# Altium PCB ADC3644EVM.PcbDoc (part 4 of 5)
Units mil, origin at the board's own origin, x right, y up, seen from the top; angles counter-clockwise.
Board outline 3900 x 2716.54 mil, 10 copper layers (Top Layer, L2 GND, L3 PWR, L4 GND, L5 SIG, L6 GND, L7 GND, L8 PWR, L9 GND, Bottom Layer), stack 61.2 mil thick; 368 components, 252 nets, 1539 pads, 1019 vias.
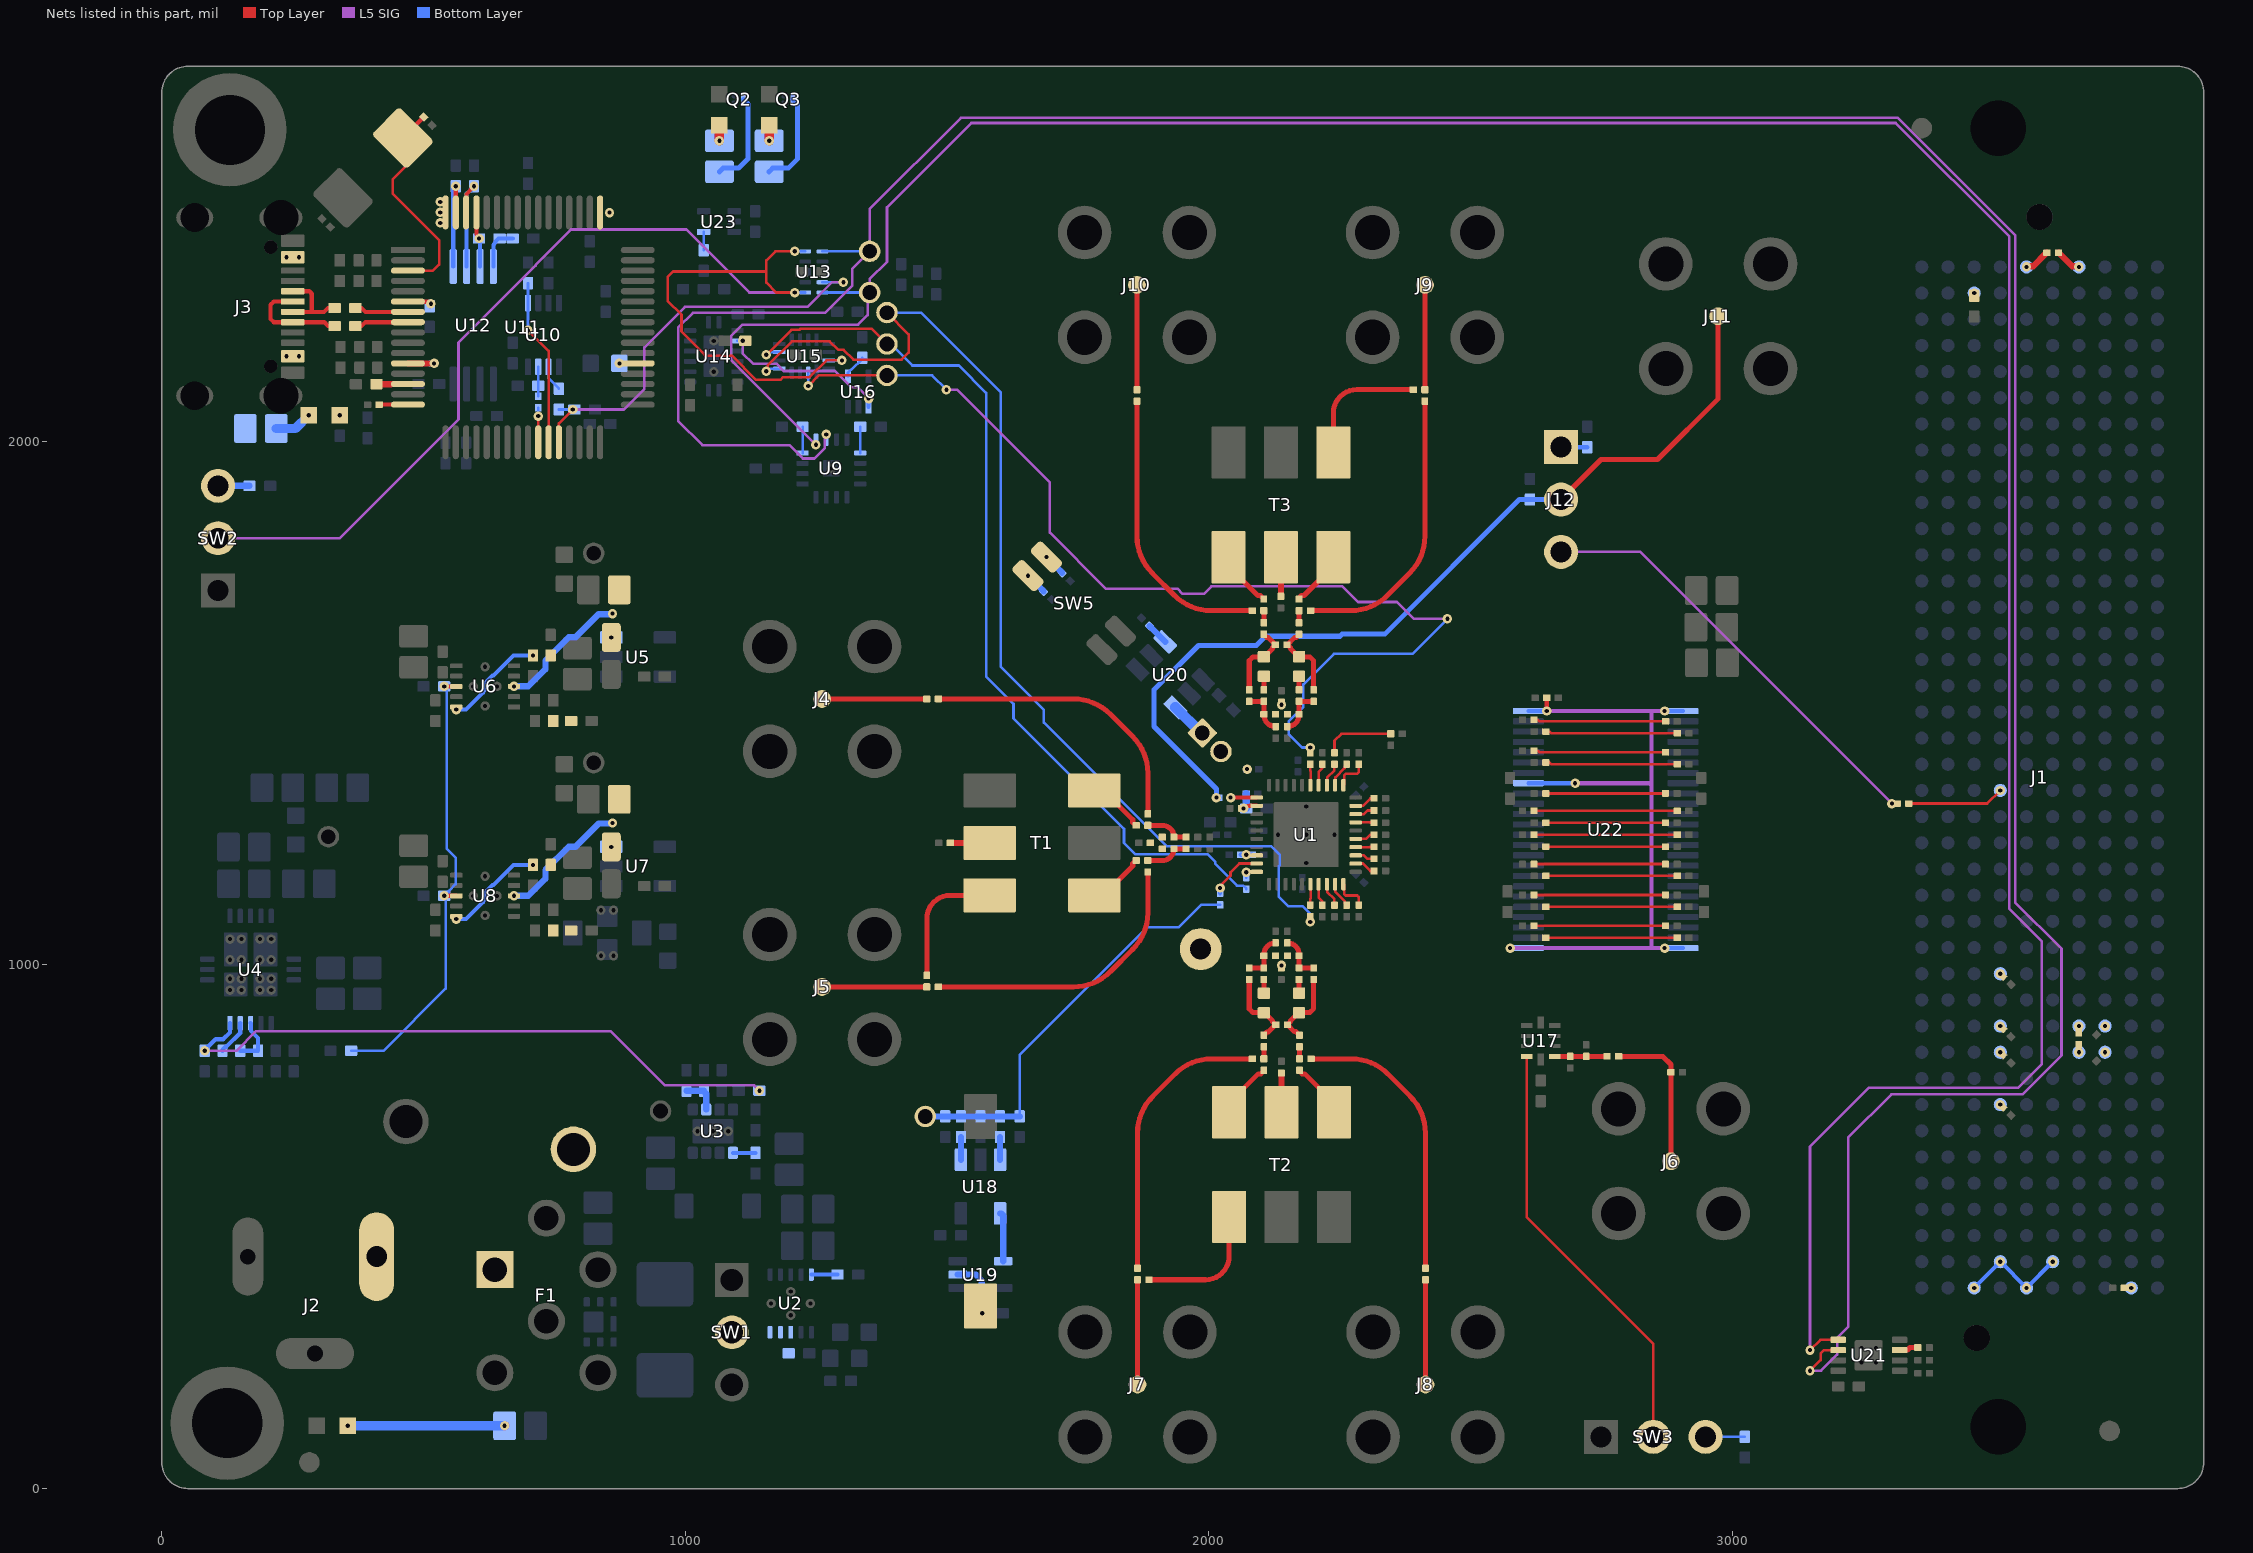
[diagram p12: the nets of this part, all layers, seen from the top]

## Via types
v1: diameter 18, hole 8, Top Layer to Bottom Layer, tented both sides, 1001 vias
v2: diameter 40, hole 20, Top Layer to Bottom Layer, tented both sides, 14 vias
v3: diameter 18, hole 8, Top Layer to Bottom Layer, tented bottom, 4 vias

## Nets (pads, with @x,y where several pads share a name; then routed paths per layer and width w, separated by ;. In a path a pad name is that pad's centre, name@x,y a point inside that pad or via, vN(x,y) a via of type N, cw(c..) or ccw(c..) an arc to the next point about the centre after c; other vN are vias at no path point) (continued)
NetC43_2: C43.2 U11.3 Y1.2 | length 411.4
  Top Layer w5: Y1.2@460.25,2579.29 465.25,2574.29 465.25,2524.93 440.9,2500.58 440.9,2472.95 529.61,2384.23 529.61,2337.89 517.8,2326.08 U11.3@470,2326.08
  Top Layer w8: Y1.2@460.25,2579.29 C43.2@500.25,2619.29
NetC48_1: C48.1 C49.2 R63.2 R65.2 | length 85.7
  Top Layer w9.7: C49.2@1883.16,1266.57 1910.93,1266.57 cw(c1910.93,1244.35) R65.2@1933.16,1244.35 C48.1@1956.16,1244.35
NetC49_1: C49.1 T1.6 | length 110.3
  Top Layer w9.7: T1.6@1781.11,1333.05 1798.61,1333.05 1854.39,1277.27 1854.39,1272.5 1860.32,1266.57 C49.1@1861.11,1266.57
NetC50_1: C50.1 T1.2 | length 75
  Top Layer w12: C50.1@1506.11,1233.05 T1.2@1581.11,1233.05
NetC51_2: C51.2 R65.1 R67.2
NetC52_1: C52.1 T1.3 | length 253.6
  Top Layer w9.7: C52.1@1461.11,980.1 1461.11,1088.05 cw(c1506.11,1088.05) 1506.11,1133.05 T1.3@1581.11,1133.05
NetC53_1: C53.1 C54.1 R67.1 R69.2 | length 85.7
  Top Layer w9.7: C53.1@1883.16,1199.53 1910.93,1199.53 ccw(c1910.93,1221.75) R67.1@1933.16,1221.75 C54.1@1956.16,1221.75
NetC53_2: C53.2 T1.4 | length 110.3
  Top Layer w9.7: T1.4@1781.11,1133.05 1798.61,1133.05 1854.39,1188.83 1854.39,1193.6 1860.32,1199.53 C53.2@1861.11,1199.53
NetC56_1: C56.1 R70.1 R72.2 U17.1 | length 100
  Top Layer w9.7: U17.1@2660.22,825.27 R70.1@2690.22,825.27 R72.2@2720.22,825.27 C56.1@2760.22,825.27
NetC56_2: C56.2 J6.1 R71.2 | length 290.9
  Top Layer w9.7: C56.2@2782.27,825.27 2866.74,825.27 2882.27,809.74 R71.2@2882.27,795.27 J6.1@2882.27,625.27
NetC57_1: C57.1 C58.1 J7.1 | length 200
  Top Layer w9.7: J7.1@1863.45,198.72 C57.1@1863.45,398.72
NetC57_2: C57.2 R74.1 | length 551.9
  Top Layer w9.7: C57.2@1863.45,420.77 1863.45,678.69 cw(c1963.45,678.69) 1892.74,749.4 1935.34,792 cw(c2004.78,722.56) 2004.78,820.77 R74.1@2082.88,820.77
NetC58_2: C58.2 T2.1 | length 253.6
  Top Layer w9.7: C58.2@1885.49,398.72 1993.45,398.72 ccw(c1993.45,443.72) 2038.45,443.72 T2.1@2038.45,518.72
NetC59_1: C59.1 T2.6 | length 110.3
  Top Layer w9.7: T2.6@2038.45,718.72 2038.45,736.22 2094.23,792 2098.99,792 2104.93,797.93 C59.1@2104.93,798.72
NetC59_2: C59.2 R74.2 R75.1 | length 23
  Top Layer w9.7: C59.2@2104.93,820.77 R75.1@2104.93,843.77
NetC60_1: C60.1 T2.5 | length 75
  Top Layer w12: T2.5@2138.45,718.72 C60.1@2138.45,793.72
NetC62_1: C62.1 L2.1 R83.2 R84.1 | length 150.7
  Top Layer w9.7: C62.1@2148.97,885.81 C62.1@2149.76,885.81 ; R83.2@2171.97,865.81 2171.97,866.6 2166.04,872.53 2163.04,872.53 C62.1@2149.76,885.81 ; R84.1@2199.97,971.43 2199.97,916.45 2192.65,909.13 2172.29,909.13 L2.1@2171.97,908.81 2170.98,908.81 2155.69,893.52 2155.69,891.74 C62.1@2149.76,885.81
NetC62_2: C62.2 L1.1 R75.2 R76.1 | length 150.7
  Top Layer w9.7: R76.1@2076.93,971.2 2076.93,916.22 2084.25,908.9 2104.61,908.9 2104.93,908.58 2105.91,908.58 2121.21,893.28 2121.21,891.51 C62.2@2127.14,885.58 ; R75.2@2104.93,865.58 2104.93,866.37 2110.86,872.3 2113.86,872.3 C62.2@2127.14,885.58 ; C62.2@2127.93,885.58 C62.2@2127.14,885.58
NetC63_1: C63.1 R82.2 R83.1 | length 23
  Top Layer w9.7: C63.1@2172.95,820.77 R83.1@2172.95,843.77
NetC63_2: C63.2 T2.4 | length 110.3
  Top Layer w9.7: C63.2@2171.97,798.72 2171.97,797.93 2177.9,792 2182.66,792 2238.45,736.22 T2.4@2238.45,718.72
NetC64_1: C64.1 J8.1 | length 200
  Top Layer w9.7: J8.1@2413.45,198.72 C64.1@2413.45,398.72
NetC64_2: C64.2 R82.1 | length 551.9
  Top Layer w9.7: R82.1@2194.02,820.77 2272.11,820.77 cw(c2272.11,722.56) 2341.56,792 2384.16,749.4 cw(c2313.45,678.69) 2413.45,678.69 C64.2@2413.45,420.77
NetC65_1: C65.1 C66.1 J9.1 | length 200
  Top Layer w9.7: C65.1@2412.46,2098.88 J9.1@2412.46,2298.88
NetC65_2: C65.2 R86.1 | length 551.9
  Top Layer w9.7: R86.1@2193.03,1676.83 2271.13,1676.83 ccw(c2271.13,1775.04) 2340.57,1705.59 2383.17,1748.19 ccw(c2312.46,1818.9) 2412.46,1818.9 C65.2@2412.46,2076.83
NetC66_2: C66.2 T3.1 | length 253.6
  Top Layer w9.7: T3.1@2237.46,1978.88 2237.46,2053.88 cw(c2282.46,2053.88) 2282.46,2098.88 C66.2@2390.42,2098.88
NetC67_1: C67.1 T3.6 | length 110.3
  Top Layer w9.7: C67.1@2170.98,1698.88 2170.98,1699.66 2176.91,1705.59 2181.68,1705.59 2237.46,1761.38 T3.6@2237.46,1778.88
NetC67_2: C67.2 R86.2 R87.1 | length 23
  Top Layer w9.7: R87.1@2171.97,1653.83 C67.2@2171.97,1676.83
NetC69_1: C69.1 T3.5 | length 75
  Top Layer w12: C69.1@2137.46,1703.88 T3.5@2137.46,1778.88
NetC70_1: C70.1 L4.1 R95.2 R96.1 | length 150.7
  Top Layer w9.7: R96.1@2076.93,1526.17 2076.93,1581.14 2084.25,1588.46 2104.61,1588.46 L4.1@2104.93,1588.78 2105.91,1588.78 2121.21,1604.08 2121.21,1605.85 C70.1@2127.14,1611.78 ; R95.2@2104.93,1631.78 2104.93,1630.99 2110.86,1625.06 2113.86,1625.06 C70.1@2127.14,1611.78 ; C70.1@2127.93,1611.78 C70.1@2127.14,1611.78
NetC70_2: C70.2 L3.1 R87.2 R88.1 | length 150.7
  Top Layer w9.7: C70.2@2148.97,1611.78 C70.2@2149.76,1611.78 ; R87.2@2171.97,1631.78 2171.97,1630.99 2166.04,1625.06 2163.04,1625.06 C70.2@2149.76,1611.78 ; R88.1@2199.97,1526.17 2199.97,1581.14 2192.65,1588.46 2172.29,1588.46 L3.1@2171.97,1588.78 2170.98,1588.78 2155.69,1604.08 2155.69,1605.85 C70.2@2149.76,1611.78
NetC71_1: C71.1 R94.2 R95.1 | length 23
  Top Layer w9.7: R95.1@2104.93,1653.83 C71.1@2104.93,1676.83
NetC71_2: C71.2 T3.4 | length 110.3
  Top Layer w9.7: T3.4@2037.46,1778.88 2037.46,1761.38 2093.24,1705.59 2098.01,1705.59 2103.94,1699.66 C71.2@2103.94,1698.88
NetC72_1: C72.1 J10.1 | length 200
  Top Layer w9.7: C72.1@1862.46,2098.88 J10.1@1862.46,2298.88
NetC72_2: C72.2 R94.1 | length 551.9
  Top Layer w9.7: C72.2@1862.46,2076.83 1862.46,1818.9 ccw(c1962.46,1818.9) 1891.75,1748.19 1934.35,1705.59 ccw(c2003.8,1775.04) 2003.8,1676.83 R94.1@2081.89,1676.83
NetD1_2: D1.2 R3.2 | length 300
  Bottom Layer w18: v1(355,120) R3.2@655,120
  other v1: 654.67,119.85
NetD4_2: D4.2 R18.2 | length 30
  Top Layer w18: v1(1065,2574.06) D4.2@1065,2604.06
NetD5_2: D5.2 R25.2 | length 30
  Top Layer w18: v1(1160,2574.06) D5.2@1160,2604.06
NetD6_2: D6.2 R45.2
  other v1: 340,2050
NetF1_1: F1.1 J2.1 TP1.1
NetFB2_1: FB2.1 R17.2 U5.3 U6.8 | length 255.5
  Bottom Layer w12: v1(672.65,1532.05) 700.02,1532.05 732.72,1564.76 732.72,1581.32 777.41,1626.01 790.09,1626.01 834.05,1669.98 859.68,1669.98 v1(860.83,1671.12)
  other v1: 858.46,1625.55
NetFB3_1: FB3.1 R27.2 U7.3 U8.8 | length 255.5
  Bottom Layer w12: v1(672.65,1132.05) 700.02,1132.05 732.72,1164.76 732.72,1181.32 777.41,1226.01 790.09,1226.01 834.05,1269.98 859.68,1269.98 v1(860.83,1271.12)
  other v1: 858.46,1225.55
NetJ1_B40: J1.B40 R145.2 | length 13.3
  Top Layer w10: R145.2@3748.13,383.27 v1(3761.42,383.27)
NetJ1_G21: J1.G21 R141.2 | length 185.4
  Top Layer w5: R141.2@3336.42,1308.27 3486.42,1308.27 v1(3511.42,1333.27)
NetJ1_G28: J1.G28 R142.2 | length 6.7
  Top Layer w5: v1(3511.42,983.27) R142.2@3516.12,978.56
NetJ1_G30: J1.G30 R143.2 | length 6.7
  Top Layer w5: v1(3511.42,883.27) R143.2@3516.12,878.56
NetJ1_G31: J1.G31 R144.2 | length 6.7
  Top Layer w5: v1(3511.42,833.27) R144.2@3516.12,828.56
NetJ1_G33: J1.G33 R146.2 | length 6.7
  Top Layer w5: v1(3511.42,733.27) R146.2@3516.12,728.56
NetJ3_A4,B4: J3.A4 J3.B4 R42.1
  other v1: 238.16,2162.69 262.16,2162.69 238.16,2351.67 262.16,2351.67
NetJ3_A6: J3.A6 J3.B6 R44.1 | length 200
  Top Layer w8: J3.B6@245.62,2227.65 213.91,2227.65 207.83,2233.72 207.83,2260.95 213.91,2267.02 J3.A6@250.16,2267.02 ; J3.B6@245.63,2227.65 J3.B6@250.16,2227.65 310.15,2227.65 317.56,2220.25 R44.1@330.16,2220.25
NetJ3_A7: J3.A7 J3.B7 R43.1 | length 155.9
  Top Layer w8: J3.A7@250.16,2247.34 286.41,2247.34 ; J3.B7@250.16,2286.71 281.72,2286.71 286.41,2282.02 286.41,2247.34 ; R43.1@330.16,2254.74 317.32,2254.74 309.91,2247.34 286.41,2247.34
NetJ11_1: J11.1 J12.2 R101.2 R118.1 | length 1725.3
  Top Layer w9.7: J12.2@2672.46,1888.88 2748.84,1965.25 2856.45,1965.25 2972.46,2081.26 J11.1@2972.46,2238.88
  Bottom Layer w9.7: R118.1@2019.37,1319.66 2014.37,1319.66 2014.37,1336.14 1895.21,1455.29 1895.21,1525.59 1979.93,1610.3 2090.5,1610.3 2107.96,1627.76 2250.14,1627.76 2254.22,1631.83 2335.71,1631.83 2592.75,1888.88 R101.2@2612.93,1888.88 J12.2@2672.46,1888.88
  other v1: 2014.16,1319.66
NetJ12_1: J12.1 R110.1 | length 50
  Bottom Layer w8: J12.1@2672.46,1988.88 R110.1@2722.46,1988.88
NetJ13_1: J13.1 U20.6 | length 69.1
  Bottom Layer w20: U20.6@1935.98,1491.88 J13.1@1984.82,1443.04
NetL1_2: L1.2 R78.1 | length 26
  Top Layer w9.7: L1.2@2104.93,946.22 R78.1@2104.93,972.22
NetL2_2: L2.2 R81.1 | length 26
  Top Layer w9.7: L2.2@2171.97,946.22 R81.1@2171.97,972.22
NetL3_2: L3.2 R90.1 | length 26
  Top Layer w9.7: R90.1@2171.97,1525.38 L3.2@2171.97,1551.38
NetL4_2: L4.2 R93.1 | length 26
  Top Layer w9.7: R93.1@2104.93,1525.38 L4.2@2104.93,1551.38
NetQ2_3: Q2.3 R18.1 | length 181.6
  Bottom Layer w9.7: R18.1@1065,2515 1071.82,2521.82 1101.43,2521.82 1119.42,2539.81 1119.42,2644.44 Q2.3@1110.75,2653.11
NetQ3_3: Q3.3 R25.1 | length 181.6
  Bottom Layer w9.7: R25.1@1160,2515 1166.82,2521.82 1196.43,2521.82 1214.42,2539.81 1214.42,2644.44 Q3.3@1205.75,2653.11
NetR1_2: R1.2 SW1.2 U2.3 U2.4 U2.5
NetR2_2: R2.2 U2.10 | length 50
  Bottom Layer w8: U2.10@1240.59,408.64 R2.2@1290.59,408.64
NetR6_1: R6.1 U3.1 | length 43
  Bottom Layer w8: U3.1@1090.88,641.15 R6.1@1133.88,641.15
NetR7_1: R7.1 R8.2 U3.6 | length 71.3
  Bottom Layer w12: R8.2@1002.1,759.83 R7.1@1035.7,759.83 1035.7,757.86 1039.7,753.86 U3.6@1039.7,723.83
NetR9_1: R9.1 R11.1 U4.24 | length 1204
  L5 SIG w5: v1(81.89,836.12) 142.5,836.12 179.96,873.58 857.24,873.58 960.83,770 1131.23,770 v1(1141.4,759.83)
  Bottom Layer w8: v1(81.89,836.12) 81.89,838.09 87.73,843.93 88.74,843.93 103.07,858.26 117.42,858.26 130.21,871.05 U4.24@130.21,888.94
NetR12_1: R12.1 R14.2 U4.22 | length 92.7
  Bottom Layer w8: R14.2@149.89,836.12 R12.1@183.89,836.12 183.89,860.44 170.5,873.83 170.5,888.02 U4.22@169.58,888.94
NetR13_2: R13.2 U4.23 | length 68.1
  Bottom Layer w8: R13.2@115.89,836.12 115.89,838.09 121.73,843.93 123.7,843.93 149.9,870.13 U4.23@149.9,888.94
NetR16_1: R16.1 R23.1 R26.1 U6.3 U8.3 | length 869.8
  Top Layer w8: v1@539.22,1132.05 U8.3@562.41,1132.05 ; v1@539.22,1532.05 U6.3@562.41,1532.05
  Bottom Layer w5: R23.1@361.48,836.12 422.94,836.12 541.95,955.13 R26.1@541.95,1129.32 ; R26.1@539.22,1132.05 541.26,1132.05 548.61,1139.39 548.61,1141.43 561.38,1154.2 561.38,1205.1 544.14,1222.33 544.14,1527.2 v1(539.3,1532.05)
  other v1: 539.3,1132.05
NetR19_1: R19.1 R20.2 U6.5 | length 206.8
  Top Layer w8: v1(562.41,1487.68) U6.5@562.41,1492.68
  Bottom Layer w8: v1(562.41,1487.68) 581.13,1487.68 612.83,1519.38 612.83,1520.55 619.35,1527.08 619.35,1540.67 631.55,1552.86 633.21,1552.86 671.45,1591.1 v1@712.72,1591.1
  other v1: 709.12,1591.1
NetR21_1: R21.1 R22.2
NetR28_1: R28.1 R29.2 U8.5 | length 206.8
  Top Layer w8: v1(562.41,1087.68) U8.5@562.41,1092.68
  Bottom Layer w8: v1(562.41,1087.68) 581.13,1087.68 612.83,1119.38 612.83,1120.55 619.35,1127.08 619.35,1140.67 631.55,1152.86 633.21,1152.86 671.45,1191.1 v1@712.72,1191.1
  other v1: 709.12,1191.1
NetR30_1: R30.1 R31.2
NetR32_1: R32.1 U9.12 | length 50
  Bottom Layer w5: U9.12@1223.78,1977.82 R32.1@1223.78,2027.82
NetR33_1: R33.1 U9.1 | length 50
  Bottom Layer w5: U9.1@1334.01,1977.82 R33.1@1334.01,2027.82
NetR36_1: R36.1 U11.16 | length 55
  Top Layer w8: R36.1@415,2070.17 U11.16@470,2070.17
NetR39_1: R39.1 U11.26 | length 65.9
  Top Layer w5: U11.26@719.02,1998.32 v1(719.02,2048.32)
  Bottom Layer w5: v1(719.02,2048.32) R39.1@719.02,2064.17
NetR40_1: R40.1 U10.6 | length 50.1
  Bottom Layer w5: U10.6@738.7,2142.22 738.7,2120.72 758.39,2101.04 R40.1@758.39,2100.25
NetR41_1: R41.1 U11.14 | length 60.1
  Top Layer w12: R41.1@410,2109.22 437.2,2109.22 437.52,2109.54 U11.14@470,2109.54
NetR43_2: R43.2 U11.7 | length 103.5
  Top Layer w8: R43.2@369.53,2254.74 381.34,2254.74 388.74,2247.34 U11.7@470,2247.34
NetR44_2: R44.2 U11.8 | length 103.5
  Top Layer w8: R44.2@369.53,2220.25 381.34,2220.25 388.74,2227.65 U11.8@470,2227.65
NetR46_2: R46.2 U11.6 | length 95.5
  Top Layer w8: v1@510,2267.02 U11.6@470,2267.02 470.73,2266.29 508.02,2266.29 511.29,2263.02 v1(514,2263.02)
  Bottom Layer w8: R46.2@510,2267.02 512,2265.02 R46.2@512,2257.98
NetR47_1: R47.1 U11.62 U12.2 | length 216.5
  Top Layer w8: U11.62@581.22,2437.3 581.67,2437.75 581.67,2472.75 v1(596.22,2487.3)
  Bottom Layer w8: U12.2@582.21,2333.95 582.21,2473.28 588.41,2479.49 590.38,2479.49 596.22,2485.33 v1(596.22,2487.3)
NetR48_1: R48.1 R50.1 U12.4 | length 84.6
  Bottom Layer w8: U12.4@633.39,2333.95 633.39,2375.6 637.48,2379.69 637.48,2381.65 643.32,2387.5 R48.1@670.29,2387.5
NetR49_1: R49.1 U11.63 U12.1 | length 205.4
  Top Layer w8: U11.63@561.54,2437.3 v1(561.54,2487.3)
  Bottom Layer w8: U12.1@556.61,2333.95 556.61,2482.38 v1(561.54,2487.3)
NetR50_2: R50.2 U11.61 U12.3 | length 106.2
  Top Layer w8: U11.61@600.91,2437.3 600.91,2395.21 605.92,2390.2 v1(605.92,2387.5)
  Bottom Layer w8: v1(605.92,2387.5) 607.8,2385.62 U12.3@607.8,2333.95
NetR51_1: R51.1 SW2.2 | length 60
  Bottom Layer w12: SW2.2@107.48,1915 R51.1@167.48,1915
NetR55_2: R55.2 U14.11 U16.1 | length 322.9
  L5 SIG w5: v1(1109.53,2192.04) 1109.53,2168.18 1129.32,2148.39 1173.78,2148.39 1187.75,2134.41 1285.79,2134.41 1316.83,2103.37 1329.42,2103.37 v1@1350,2082.79
  Bottom Layer w5: U14.11@1099.53,2192.04 v1(1109.53,2192.04)
  Bottom Layer w8: U16.1@1350,2065.97 v1@1350,2079.15
  other v1: 1350,2081.71
NetR57_1: R57.1 U16.4 | length 47.4
  Bottom Layer w5: U16.4@1310.63,2124.23 1310.63,2131.52 1315.96,2136.85 1317.13,2136.85 1337.95,2157.67 R57.1@1337.95,2159.64
NetR63_1: R63.1 R64.2 | length 551.9
  Top Layer w9.7: R64.2@1483.16,1508.05 1741.08,1508.05 cw(c1741.08,1408.05) 1811.79,1478.76 1854.39,1436.16 cw(c1784.95,1366.72) 1883.16,1366.72 R63.1@1883.16,1288.62
NetR68_2: R68.2 R69.1 | length 551.9
  Top Layer w9.7: R68.2@1483.16,958.05 1741.08,958.05 ccw(c1741.08,1058.05) 1811.79,987.34 1854.39,1029.94 ccw(c1784.95,1099.38) 1883.16,1099.38 R69.1@1883.16,1177.48
NetR73_1: R73.1 SW3.2 | length 75
  Bottom Layer w5: SW3.2@2948.45,98.72 R73.1@3023.45,98.72
NetR76_2: R76.2 R77.1 R78.2 R79.2 | length 88.7
  Top Layer w9.7: R76.2@2076.93,994.26 R78.2@2104.93,994.26 R79.2@2104.93,1017.26 2104.93,1020.04 cw(c2127.15,1020.04) R77.1@2127.15,1042.26
NetR80_1: R80.1 R81.2 R84.2 R85.1 | length 88.7
  Top Layer w9.7: R85.1@2149.75,1042.26 cw(c2149.75,1020.04) 2171.97,1020.04 R80.1@2171.97,1017.26 R81.2@2171.97,994.26 R84.2@2199.97,994.26
NetR88_2: R88.2 R89.1 R90.2 R91.2 | length 88.7
  Top Layer w9.7: R89.1@2149.75,1455.33 ccw(c2149.75,1477.56) 2171.97,1477.56 2171.97,1480.33 R90.2@2171.97,1503.33 R88.2@2199.97,1503.33
NetR92_1: R92.1 R93.2 R96.2 R97.1 | length 88.7
  Top Layer w9.7: R96.2@2076.93,1503.33 R93.2@2104.93,1503.33 2104.93,1480.33 2104.93,1477.56 ccw(c2127.15,1477.56) R97.1@2127.15,1455.33
NetR98_1: R98.1 U1.25 | length 38.3
  Top Layer w5: U1.25@2280.18,1240.92 2300.22,1240.92 2308.09,1248.8 R98.1@2315.18,1248.8
NetR99_1: R99.1 U1.17 | length 43
  Top Layer w5: U1.17@2209.31,1154.31 2209.31,1128.74 2216.66,1121.4 R99.1@2216.66,1114.31
NetR100_1: R100.1 U1.18 | length 46.1
  Top Layer w5: U1.18@2225.06,1154.31 2225.6,1153.77 2225.6,1139.65 2239.28,1125.97 2239.28,1114.78 R100.1@2239.76,1114.31
NetR102_1: R102.1 U1.19 | length 49.1
  Top Layer w5: U1.19@2240.81,1154.31 2241.29,1153.83 2241.29,1139.59 2259.06,1121.82 2259.06,1118.11 R102.1@2262.86,1114.31
NetR103_1: R103.1 U1.20 | length 65.1
  Top Layer w5: U1.20@2256.56,1154.31 2257.99,1152.87 2257.99,1135.62 2260.92,1132.69 2283.03,1132.69 2285.96,1129.76 R103.1@2285.96,1114.31
NetR104_1: R104.1 U1.22 | length 40.9
  Top Layer w5: U1.22@2280.18,1193.68 2293.91,1193.68 2308.09,1179.5 R104.1@2315.18,1179.5
NetR105_1: R105.1 U1.23 | length 37.8
  Top Layer w5: U1.23@2280.18,1209.43 2295.86,1209.43 2302.69,1202.6 R105.1@2315.18,1202.6
NetR106_1: R106.1 U1.24 | length 35.2
  Top Layer w5: U1.24@2280.18,1225.18 2307.57,1225.18 2308.09,1225.7 R106.1@2315.18,1225.7
NetR111_1: R111.1 U1.34 | length 43
  Top Layer w5: U1.34@2209.31,1343.29 2209.31,1368.85 2216.66,1376.2 R111.1@2216.66,1383.29
NetR112_1: R112.1 U1.33 | length 46.1
  Top Layer w5: U1.33@2225.06,1343.29 2225.6,1343.83 2225.6,1357.95 2239.28,1371.63 2239.28,1382.81 R112.1@2239.76,1383.29
NetR112_2: R112.2 R123.2 R127.2 | length 136
  Top Layer w5: R112.2@2239.76,1405.33 2239.76,1428.52 2252.74,1441.5 R127.2@2347.23,1441.5
NetR113_1: R113.1 U1.32 | length 49.1
  Top Layer w5: U1.32@2240.81,1343.29 2241.29,1343.77 2241.29,1358 2259.06,1375.77 2259.06,1379.49 R113.1@2262.86,1383.29
NetR114_1: R114.1 U1.31 | length 65.1
  Top Layer w5: U1.31@2256.56,1343.29 2257.99,1344.72 2257.99,1361.98 2260.92,1364.91 2283.03,1364.91 2285.96,1367.84 R114.1@2285.96,1383.29
NetR115_1: R115.1 U1.29 | length 40.9
  Top Layer w5: U1.29@2280.18,1303.92 2293.91,1303.92 2308.09,1318.09 R115.1@2315.18,1318.1
NetR116_1: R116.1 U1.28 | length 37.8
  Top Layer w5: U1.28@2280.18,1288.17 2295.86,1288.17 2302.69,1295 R116.1@2315.18,1295
NetR117_1: R117.1 U1.27 | length 35.2
  Top Layer w5: U1.27@2280.18,1272.42 2307.57,1272.42 2308.09,1271.9 R117.1@2315.18,1271.9
NetR118_2: R118.2 U1.1 | length 50
  Top Layer w8: v1(2041.2,1319.66) U1.1@2091.2,1319.66
NetR119_2: R119.2 U1.9 | length 108.2
  Top Layer w5: v1(2021.2,1146.93) 2019.8,1146.93 2018.69,1148.05 2018.8,1148.05 2026.06,1155.3 2026.06,1155.41 2041.2,1170.56 2041.2,1176.93 2057.95,1193.68 U1.9@2091.2,1193.68
  Bottom Layer w8: R119.2@2021.2,1136.93 v1(2021.2,1146.93)
NetR121_2: R121.2 U18.1 | length 43.5
  Bottom Layer w12: U18.1@1526.21,627.87 R121.2@1526.21,671.34
NetR122_2: R122.2 SW4.1 U19.2 | length 113.2
  Bottom Layer w12: U19.2@1520.3,408.64 1554.43,408.64 1566.22,396.85 1566.22,335.65 v1(1567.09,334.78)
NetR125_2: R125.2 U1.35 | length 40.6
  Top Layer w5: U1.35@2193.56,1343.29 2194.32,1344.04 2194.32,1370.12 2193.56,1370.87 R125.2@2193.56,1383.29
NetR126_2: R126.2 U1.10 | length 30.4
  Top Layer w5: v1(2071.2,1176.93) 2072.2,1177.93 U1.10@2091.2,1177.93
  Bottom Layer w5: R126.2@2071.2,1166.93 v1(2071.2,1176.93)
NetR128_2: R128.2 U18.3 | length 43.5
  Bottom Layer w12: U18.3@1601.01,627.87 R128.2@1601.01,671.34
NetR129_2: R129.2 U1.16 | length 40.6
  Top Layer w5: R129.2@2193.56,1114.31 2193.56,1126.72 2194.32,1127.47 2194.32,1153.56 U1.16@2193.56,1154.31
NetR130_1: R130.1 SW5.1 | length 42.4
  Bottom Layer w12: v1(1654.13,1743.53) R130.1@1684.13,1713.53
NetR131_1: R131.1 U20.3 | length 42.4
  Bottom Layer w12: R131.1@1886.5,1647.16 U20.3@1916.5,1617.16
NetR133_2: R133.2 SW5.2 | length 42.4
  Bottom Layer w12: v1(1689.48,1778.88) R133.2@1719.48,1748.88
NetR136_2: R136.2 U21.3 | length 37.1
  Top Layer w10: U21.3@3319.06,264.36 3333.82,264.36 3338.82,269.36 R136.2@3354.06,269.36
NetR149_1: R149.1 U23.4 | length 35
  Bottom Layer w5: R149.1@1034.92,2365.12 U23.4@1034.92,2400.12
NetR151_1: R151.1 R182.2 U22.1 U22.24 U22.25 U22.41 U22.48 | length 1375.2
  Top Layer w8: v1(2645,1485.02) R151.1@2645,1510.29
  L5 SIG w8: v1(2575,1032.26) 2845,1032.26 ; v1(2645,1485.02) 2845,1485.02 ; v1(2699.16,1347.22) 2841.06,1347.22 2845,1343.29 ; v1(2870.28,1032.26) 2845,1032.26 ; v1(2870.28,1485.02) 2845,1485.02 ; 2845,1032.26 2845,1343.29 ; 2845,1343.29 2845,1485.02
  Bottom Layer w8: v1(2575,1032.26) U22.25@2610,1032.26 ; U22.41@2610,1347.22 v1(2699.16,1347.22) ; U22.48@2610,1485.02 v1(2645,1485.02) ; v1(2870.28,1032.26) U22.24@2905.28,1032.26 ; v1(2870.28,1485.02) U22.1@2905.28,1485.02
NetR152_2: R152.2 R153.1 | length 251.2
  Top Layer w5: R152.2@2620.76,1133.69 R153.1@2871.95,1133.69
NetR154_2: R154.2 R155.1 | length 251.2
  Top Layer w5: R154.2@2643.33,1111 R155.1@2894.51,1111
NetR156_2: R156.2 R157.1 | length 251.2
  Top Layer w5: R156.2@2620.76,1074.63 R157.1@2871.95,1074.63
NetR158_2: R158.2 R159.1 | length 251.2
  Top Layer w5: R158.2@2643.33,1051.95 R159.1@2894.51,1051.95
NetR160_2: R160.2 R161.1 | length 251.2
  Top Layer w5: R160.2@2643.33,1170.06 R161.1@2894.51,1170.06
NetR162_2: R162.2 R163.1 | length 251.2
  Top Layer w5: R162.2@2620.76,1192.74 R163.1@2871.95,1192.74
NetR164_2: R164.2 R165.1 | length 228.6
  Top Layer w5: R164.2@2643.33,1226.11 R165.1@2871.95,1226.11
NetR166_2: R166.2 R167.1 | length 273.7
  Top Layer w5: R166.2@2620.76,1248.8 R167.1@2894.51,1248.8
NetR168_2: R168.2 R169.1 | length 252.5
  Top Layer w5: R168.2@2620.76,1468.33 2627.85,1468.33 2630.85,1465.33 R169.1@2872.01,1465.33
NetR170_2: R170.2 R171.1 | length 252.5
  Top Layer w5: R170.2@2643.33,1445.65 2650.42,1445.65 2653.42,1442.65 R171.1@2894.58,1442.65
NetR172_2: R172.2 R173.1 | length 252.4
  Top Layer w5: R172.2@2620.76,1409.28 2627.85,1409.28 2630.85,1406.28 R173.1@2871.95,1406.28
NetR174_2: R174.2 R175.1 | length 252.4
  Top Layer w5: R174.2@2643.33,1386.59 2650.42,1386.59 2653.42,1383.59 R175.1@2894.51,1383.59
NetR176_2: R176.2 R177.1 | length 228.6
  Top Layer w5: R176.2@2643.33,1327.54 R177.1@2871.95,1327.54
NetR178_2: R178.2 R179.1 | length 273.7
  Top Layer w5: R178.2@2620.76,1294.17 R179.1@2894.51,1294.17
NetR180_2: R180.2 R181.1 | length 228.6
  Top Layer w5: R180.2@2643.33,1271.48 R181.1@2871.95,1271.48
NetSW2_1: SW2.1 U13.1 U13.5 U15.15 | length 2403.3
  Top Layer w5: v1(1208.98,2284.23) 1173.35,2284.23 1154.53,2303.05 1154.53,2345.64 ; v1(1208.98,2362.97) 1171.86,2362.97 1154.53,2345.64 ; v1(1299.02,2154.64) 1269.38,2154.64 1237.25,2122.52 1186.32,2122.52 1181.19,2117.39 1134.92,2117.39 1088.67,2163.64 1038.73,2163.64 992.48,2209.89 992.48,2242.28 966.29,2268.47 966.29,2314.4 976.23,2324.34 1154.53,2324.34 1154.53,2345.64
  L5 SIG w5: SW2.1@107.48,1815 340,1815 566.72,2041.72 566.72,2188.52 713.83,2335.63 713.83,2337.27 781.12,2404.56 1001.89,2404.56 1122.22,2284.23 v1(1208.98,2284.23)
  Bottom Layer w5: v1(1208.98,2284.23) U13.1@1228.98,2284.23 ; v1(1208.98,2362.97) U13.5@1228.98,2362.97 ; U15.15@1274.02,2154.64 v1(1299.02,2154.64)
NetSW3_1: SW3.1 U17.9 | length 826.5
  Top Layer w5: U17.9@2607.07,825.27 2607.07,518.12 2848.45,276.74 SW3.1@2848.45,98.72
NetU18_4: U18.4 U19.4 | length 94.7
  Bottom Layer w12: U18.4@1601.01,525.51 cw(c1601.01,519.61) 1606.92,519.61 U19.4@1606.92,434.23
PDN/SYNC: J12.3 R141.1 | length 841
  Top Layer w5: v1(3304.37,1308.27) R141.1@3314.37,1308.27
  L5 SIG w5: J12.3@2672.46,1788.88 2823.76,1788.88 v1(3304.37,1308.27)
PG-C2M: J1.D1 R137.2 | length 50
  Top Layer w12: R137.2@3622.44,2360 3623.23,2360 3648.81,2334.42 3660.27,2334.42 v1(3661.42,2333.27)
PG-M2C: J1.F1 R137.1 | length 50
  Top Layer w12: v1(3561.42,2333.27) 3562.57,2334.42 3574.02,2334.42 3599.61,2360 R137.1@3600.39,2360
PRSNT-M2C-L: J1.H2 R150.2 | length 5.3
  Top Layer w10: R150.2@3461.42,2277.95 v1(3461.42,2283.27)
RESET: C80.2 PP10.1 R119.1 R120.1 R121.1 R124.2 R128.1 | length 798.9
  Bottom Layer w5: R124.2@1638.41,710.71 1638.41,827.76 1882.91,1072.26 1942.44,1072.26 1985.06,1114.88 R119.1@2021.2,1114.88
  Bottom Layer w12: PP10.1@1458.21,710.71 R121.1@1526.21,710.71 C80.2@1563.61,710.71 ; C80.2@1563.7,710.62 1628.47,710.62 1628.57,710.71 R124.2@1638.41,710.71
SCL_I2C: PP6.1 U9.14 U13.6 U21.6 | length 6133.7
  Top Layer w5: v1(3147.87,225) 3168.23,245.35 3168.23,257.77 3174.82,264.36 U21.6@3201.8,264.36
  L5 SIG w5: v1(1269.05,2013.41) 1266.57,2010.92 1266.57,2003.87 1265.87,2003.17 1265.87,1986.58 1246.61,1967.32 1224.4,1967.32 1199.09,1992.63 1032.58,1992.63 986.08,2039.13 986.08,2217.17 1014.43,2245.51 1266.78,2245.51 1318.35,2297.08 1318.35,2329.47 PP6.1@1351.85,2362.97 1351.85,2443.99 1525.94,2618.09 3315.56,2618.09 3539.7,2393.95 3539.7,1119.7 3628.21,1031.19 3628.21,827.47 3553.52,752.78 3303.53,752.78 3220.91,670.17 3220.91,308.82 3199.85,287.76 3199.85,255.56 3169.29,225 v1(3147.87,225)
  Bottom Layer w5: U13.6@1261.85,2362.97 PP6.1@1351.85,2362.97
SCL_Local: J1.C30 R139.2
  other v1: 3711.42,883.27
SCLK_DUT: PP7.1 R125.1 U15.2 | length 2010
  Top Layer w5: v1(1234.65,2106.02) 1254.59,2125.97 PP7.1@1385,2125.97 ; R125.1@2193.56,1405.33 v1(2193.56,1415.33)
  L5 SIG w5: v1(1498.58,2098.63) 1518.8,2098.63 1695.96,1921.47 1695.96,1825.49 1802.59,1718.87 1939.67,1718.87 1949.59,1708.94 1990.32,1708.94 2004.43,1723.05 2254.88,1723.05 2284.68,1693.25 2359.14,1693.25 2391.31,1661.08 v1(2455.46,1661.08)
  Bottom Layer w5: v1(1234.65,2106.02) U15.2@1234.65,2131.02 ; PP7.1@1385,2125.97 1471.24,2125.97 v1(1498.58,2098.63) ; v1(2193.56,1415.33) 2178.12,1415.33 2152.3,1441.16 2152.3,1465.05 2180.18,1492.93 2180.18,1536.02 2238.45,1594.29 2388.67,1594.29 v1(2455.46,1661.08)
SDA_I2C: PP5.1 U9.13 U13.10 U21.5 | length 5728.6
  Top Layer w5: v1(3147.87,264.37) 3167.55,284.05 3168.23,284.05 U21.5@3201.8,284.05
  L5 SIG w5: v1(1249.37,1993.41) 1087.29,2155.49 1087.29,2201.16 1108.93,2222.79 1329.99,2222.79 1348.2,2241 1348.2,2280.58 PP5.1@1351.85,2284.23 1351.85,2309.78 1385,2342.93 1385,2446.97 1546.11,2608.09 3311.42,2608.09 3528.65,2390.86 3528.65,1107.02 3590.66,1045 3590.66,810.66 3545.25,765.24 3259.96,765.24 3147.87,653.16 v1(3147.87,264.37)
  Bottom Layer w5: U13.10@1261.85,2284.23 PP5.1@1351.85,2284.23
SDA_Local: J1.C31 R140.2
  other v1: 3711.42,833.27
SDIO_DUT: PP9.1 R126.1 U15.7 | length 1759.6
  Top Layer w5: v1(1154.53,2165.39) 1202.18,2213.04 1218.07,2213.04 1219.95,2214.92 1356.05,2214.92 PP9.1@1385,2185.97
  Bottom Layer w5: v1(1154.53,2165.39) 1157.23,2165.39 1162.23,2170.39 U15.7@1179.53,2170.39 ; PP9.1@1385,2185.97 1392.55,2185.97 1433.53,2144.99 1522.19,2144.99 1574.47,2092.72 1574.47,1550.75 1626.54,1498.67 1626.54,1470.95 1837.61,1259.88 1837.61,1233.17 1859.03,1211.75 1997.21,1211.75 2011.68,1197.28 2011.68,1193.42 2053.49,1151.6 2065.27,1151.6 2071.2,1145.67 R126.1@2071.2,1144.88
SEN_DUT: PP8.1 R129.1 U15.5 | length 2122.3
  Top Layer w5: v1(1154.53,2133.89) 1157.02,2136.38 1157.02,2144.54 1203.61,2191.14 1275.68,2191.14 1292.18,2174.64 1302.35,2174.64 1320.99,2156 1413.04,2156 1426.4,2169.36 1426.4,2204.56 PP8.1@1385,2245.97 ; v1(2193.56,1082.26) R129.1@2193.56,1092.26
  Bottom Layer w5: v1(1154.53,2133.89) 1157.23,2133.89 1162.23,2138.89 U15.5@1179.53,2138.89 ; PP8.1@1385,2245.97 1449.66,2245.97 1602.43,2093.19 1602.43,1569.45 1684.54,1487.34 1684.54,1463.02 1784.28,1363.29 1784.28,1361.98 1919.33,1226.93 2118.71,1226.93 2135.43,1210.22 2135.43,1190.34 2133.12,1188.03 2133.12,1131.01 2152.3,1111.84 2179.36,1111.84 2193.56,1097.63 v1(2193.56,1082.26)
SMA_CLK_N: C52.2 J5.1 R68.1 | length 200
  Top Layer w9.7: J5.1@1261.11,958.05 C52.2@1461.11,958.05
SMA_CLK_P: J4.1 R64.1 | length 200
  Top Layer w9.7: J4.1@1261.11,1508.05 R64.1@1461.11,1508.05
TDI_FMC: J1.D30 R138.2 | length 13.3
  Top Layer w10: R138.2@3661.42,869.98 v1(3661.42,883.27)
TDO_FMC: J1.D31 R138.1 | length 14.7
  Top Layer w10: v1(3661.42,833.27) R138.1@3661.42,847.93
USB_5V: D6.1 R42.2 | length 72.4
  Bottom Layer w18: R42.2@218.64,2024.59 255.06,2024.59 v1(280.47,2050)
USB_I2C_SCL: R34.1 R39.2 U10.7 | length 56
  Bottom Layer w5: R39.2@719.02,2086.22 719.02,2093.3 R34.1@719.02,2106.22 719.02,2116.06 U10.7@719.02,2142.22
USB_I2C_SDAr: R38.2 R40.2 U11.28 U13.9 | length 804.4
  Top Layer w5: U11.28@758.39,1998.32 758.39,2034.35 v1(784.92,2060.88)
  L5 SIG w5: v1(784.92,2060.88) 882.7,2060.88 921.46,2099.64 921.46,2179.39 999.16,2257.09 1233.54,2257.09 1280.35,2303.91 v1(1301.85,2303.91)
  Bottom Layer w5: R40.2@758.39,2060.88 v1(784.92,2060.88) ; U13.9@1261.85,2303.91 v1(1301.85,2303.91)
USB_I2C_SDAw: R37.1 U10.1 U11.27 | length 320.3
  Top Layer w5: v1(699.33,2211.86) 738.7,2172.49 U11.27@738.7,1998.32
  Bottom Layer w5: v1(699.33,2211.86) U10.1@699.33,2264.27 R37.1@699.33,2302.27
VADJ: J1.E39 J1.F40 J1.G39 J1.H40 | length 212.1
  Bottom Layer w8: v1(3461.42,383.27) v1(3511.42,433.27) v1(3561.42,383.27) v1(3611.42,433.27)
VCM: C61.2 C68.2 C78.2 C79.2 R79.1 R80.2 R91.1 R92.2 TP3.1 U1.8 | length 42.1
  Top Layer w5: v1(2071.2,1210.43) 2072.2,1209.43 U1.8@2091.2,1209.43
  Bottom Layer w9: C78.2@2060.77,1210.43 v1(2071.2,1210.43) C79.2@2082.49,1210.43
  other v1: 2138.45,999.26 2138.45,1496.94
VCORE: C35.2 U11.12 U11.37 U11.49 U11.64 | length 92.5
  Top Layer w5: v1(873.98,2148.91) U11.37@908.5,2148.91
  Top Layer w12: U11.12@470,2148.91 v1(520,2148.91)
  Bottom Layer w12: v1@512,2148.91 v1(520,2148.91)
  other v1: 531.85,2417.3 855,2436.85 531.85,2437.3 531.85,2457.3
VREF: C82.2 C83.2 C84.2 J13.2 R132.2 U1.2 | length 63.3
  Top Layer w8: C84.2@2062.2,1298.92 v1(2066.2,1298.92) cw(c2078.27,1286.84) 2078.27,1303.92 U1.2@2091.2,1303.92
  Bottom Layer w8: v1(2066.2,1298.92) C82.2@2071.2,1298.92
  Bottom Layer w14: C82.2@2071.2,1298.92 C83.2@2071.2,1326.92
  other v1: 2072.72,1374.15
pads on no net: FID1.1 FID2.1 FID3.1 H1. H3. J1. J1.A2 J1.A3 J1.A6 J1.A7 J1.A10 J1.A11 J1.A14 J1.A15 J1.A18 J1.A19 J1.A22 J1.A23 J1.A26 J1.A27 J1.A30 J1.A31 J1.A34 J1.A35 J1.A38 J1.A39 J1.B1 J1.B4 J1.B5 J1.B8 J1.B9 J1.B12 J1.B13 J1.B16 J1.B17 J1.B20 J1.B21 J1.B24 J1.B25 J1.B28 J1.B29 J1.B32 J1.B33 J1.B36 J1.B37 J1.C2 J1.C3 J1.C6 J1.C7 J1.C11 J1.C14 J1.C15 J1.C19 J1.C22 J1.C23 J1.C26 J1.C27 J1.C39 J1.D4 J1.D5 J1.D9 J1.D12 J1.D15 J1.D18 J1.D20 J1.D21 J1.D23 J1.D24 J1.D26 J1.D27 J1.D29 J1.D33 J1.D34 J1.D36 J1.D38 J1.D40 J1.E2 J1.E3 J1.E6 J1.E7 J1.E9 J1.E10 J1.E12 J1.E13 J1.E15 J1.E16 J1.E18 J1.E19 J1.E21 J1.E22 J1.E24 J1.E25 J1.E27 J1.E28 J1.E30 J1.E31 J1.E33 J1.E34 J1.E36 J1.E37 J1.F4 J1.F5 J1.F7 J1.F8 J1.F10 J1.F11 J1.F13 J1.F14 J1.F16 J1.F17 J1.F19 J1.F20 J1.F22 J1.F23 J1.F25 J1.F26 J1.F28 J1.F29 J1.F31 J1.F32 J1.F34 J1.F35 J1.F37 J1.F38 J1.G2 J1.G3 J1.G7 J1.G10 J1.G13 J1.G16 J1.G18 J1.G19 J1.G22 J1.G24 J1.G25 J1.G27 J1.G34 J1.G36 J1.G37 J1.H1 J1.H5 J1.H8 J1.H11 J1.H14 J1.H17 J1.H20 J1.H22 J1.H23 J1.H25 J1.H26 J1.H28 J1.H29 J1.H31 J1.H32 J1.H34 J1.H35 J1.H37 J1.H38 J1.J2 J1.J3 J1.J6 J1.J7 J1.J9 J1.J10 J1.J12 J1.J13 J1.J15 J1.J16 J1.J18 J1.J19 J1.J21 J1.J22 J1.J24 J1.J25 J1.J27 J1.J28 J1.J30 J1.J31 J1.J33 J1.J34 J1.J36 J1.J37 J1.J39 J1.K1 J1.K4 J1.K5 J1.K7 J1.K8 J1.K10 J1.K11 J1.K13 J1.K14 J1.K16 J1.K17 J1.K19 J1.K20 J1.K22 J1.K23 J1.K25 J1.K27 J1.K28 J1.K29 J1.K31 J1.K32 J1.K34 J1.K35 J1.K37 J1.K38 J1.K40 J3. J3.A5 J3.A8 J3.B5 J3.B8 Q1.0 Q2.1@1095,2645.24 Q2.2@1095,2660.98 Q3.1@1190,2645.24 Q3.2@1190,2660.98 R107.1 R107.2 R108.1 R108.2 R109.1 R109.2 SH-J12.0 U2.9 U3.0 U4.4 U11.21 U11.22 U11.23 U11.24 U11.29 U11.30 U11.32 U11.33 U11.34 U11.36 U11.38 U11.39 U11.40 U11.41 U11.43 U11.44 U11.45 U11.46 U11.48 U11.52 U11.53 U11.54 U11.55 U11.57 U11.58 U11.59 U11.60 U12.6 U12.7 U13.3@1228.98,2323.6 U13.8@1261.85,2323.6 U15.10 U15.11 U15.12 U17.2 U17.4 U17.7 U20.5 U22.8

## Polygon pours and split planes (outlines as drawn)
GND on L8 PWR "L2 GND-GND" (solid, remove dead copper, pour order 92): 3900,-3.61 3900,2716.53 556.54,2716.54 ccw(c556.53,2660.06) 536.65,2712.92 56.54,2712.92 ccw(c56.53,2656.39) 0,2656.39 0,46.39 ccw(c50,46.39) 50,-3.61
3p3V_Utility on L8 PWR "L8 PWR-3p3V_Utility" (solid, remove dead copper, pour order 85): 155,760 265,760 265,1015 595,1015 595,605.64 1290,605.64 1290,416.86 786.24,416.86 786.24,-5 3320,-5 3320,100 1035,100 1035,248.29 3145,248.29 3145,2015 1389.6,2015 1389.6,2545 1390,2545 1390,2716.54 1265,2716.54 1265,2622.3 155,2622.3
2p3V on L8 PWR "vcm" (solid, remove dead copper, pour order 55): 170,1140 560,1140 560,1422.72 496.81,1422.72 496.81,1505.28 570,1505.28 570,1705 170,1705
1p8V_BUFVCC on L8 PWR "1" (solid, pour order 27): 965,1115 965,845 2385,845 2385,980 3145,980 3145,1665 2235,1665 2235,1375 980,1375 980,1115
12V on L8 PWR "L8 PWR-12V" (solid, remove dead copper, pour order 34): 0,-5 275,-5 275.6,-5 790,-5 790,416.86 1290,416.86 1290,605.64 595,605.64 595,1015 275.6,1015 275.6,745 140,745 140,2635 1257.39,2635 1257.39,2715 0,2715
1p8V_LVLSHIFT on L8 PWR "1" (solid, pour order 24): 1580,1639.12 1755,1639.12 1755,2415 1405,2415 1405,1640 1580,1640
12V_FMC on L8 PWR "gnd" (solid, remove dead copper, pour order 81): 3635,660 3791.17,660 3791.17,105 997.3,105 997.3,253.29 2785,253.29 3635,253.29
VCORE on L8 PWR "L10 PWR-VCORE" (solid, remove dead copper, pour order 69): 948.98,2112.51 948.98,2470 637.92,2470 637.92,2479.2 470,2479.2 470,2126.19 637.92,2126.19 637.92,2410 876.5,2410 876.5,2192.06 845,2192.06 845,2112.51
GND on L5 SIG "L2 GND-GND" (solid, remove dead copper, pour order 93): 3900,-3.61 3900,2716.53 556.54,2716.54 ccw(c556.53,2660.06) 536.65,2712.92 56.54,2712.92 ccw(c56.53,2656.39) 0,2656.39 0,46.39 ccw(c50,46.39) 50,-3.61
GND on L5 SIG "gnd" (solid, remove dead copper, pour order 54): 1895,1450 1895,1235 2130,1235 2130,1450
VCM on L5 SIG "L5 SIG-VCM" (solid, remove dead copper, pour order 42): 1885,945 2468.65,945 2468.65,1540 2080,1540 2080,1450 2130,1450 2130,1235 1885,1235
VREF on L5 SIG "gnd" (solid, remove dead copper, pour order 39): 1978.88,1424.46 1978.88,1285 2085.6,1285 2085.6,1424.46
EXTGND on L5 SIG "NONET_L-01_P-001" (solid, remove dead copper, pour order 38): 688.31,766.34 0,766.34 0,50 ccw(c50,50) 50,0 688.31,0
GND on L3 PWR "L2 GND-GND" (solid, remove dead copper, pour order 90): 3900,-3.61 3900,2716.53 556.54,2716.54 ccw(c556.53,2660.06) 536.65,2712.92 56.54,2712.92 ccw(c56.53,2656.39) 0,2656.39 0,46.39 ccw(c50,46.39) 50,-3.61
1p8V_AVDD on L3 PWR "L3 PWR-1p8V_AVDD" (solid, remove dead copper, pour order 51): 2018.18,936.33 2018.64,879.73 2333.72,879.73 2333.72,936.33 2198.25,936.33 2198.25,1785 385,1785 385,1435 2018.64,1435 2018.64,936.33
1p8V_LVLSHIFT on L3 PWR "L3 PWR-1p8V_LVLSHIFT" (solid, pour order 44): 2636.58,697.88 3106.62,697.88 3106.62,2712.92 0,2712.92 0,887.5 1224.31,887.5 1224.31,0 1659.39,0 1659.39,1188.15 1366.99,1188.15 709.12,1191.1 269.17,1191.1 269.17,2033.32 2636.58,2033.32
3p3V_EEPROM on L3 PWR "vcm" (solid, remove dead copper, pour order 65): 3270,340 2875,340 2875,0 3270,0 3270,100
3p3V_AUX on L3 PWR "vcm" (solid, remove dead copper, pour order 52): 3270,340 3270,0 3900,0 3900,820 3575,820 3575,340
1p8V_IOVDD on L3 PWR "L3_PWR_1P8V_IOVDD_P073" (solid, remove dead copper, pour order 73): 385,1205.06 1741.07,1205.06 1741.07,376.16 2621.28,376.16 2621.28,1419.71 2263.63,1419.71 2263.63,819.66 1994.38,819.66 1994.38,1381.33 385,1381.33
EXTGND on L3 PWR "NONET_L-01_P-001" (solid, remove dead copper, pour order 45): 688.31,766.34 0,766.34 0,50 ccw(c50,50) 50,0 688.31,0
GND on L2 GND "L2 GND-GND" (solid, remove dead copper, pour order 71): 3900,-3.61 3900,2716.53 556.54,2716.54 ccw(c556.53,2660.06) 536.65,2712.92 56.54,2712.92 ccw(c56.53,2656.39) 0,2656.39 0,46.39 ccw(c50,46.39) 50,-3.61
EXTGND on L2 GND "NONET_L-01_P-001" (solid, remove dead copper, pour order 7): 688.31,766.34 0,766.34 0,50 ccw(c50,50) 50,0 688.31,0
GND on Top Layer "L2 GND-GND" (solid, remove dead copper, pour order 87): 3900,-3.61 3900,2716.53 556.54,2716.54 ccw(c556.53,2660.06) 536.65,2712.92 56.54,2712.92 ccw(c56.53,2656.39) 0,2656.39 0,46.39 ccw(c50,46.39) 50,-3.61
EXTGND on Top Layer "NONET_L-01_P-001" (solid, remove dead copper, pour order 58): 688.31,766.34 0,766.34 0,50 ccw(c50,50) 50,0 688.31,0
GND on L6 GND "L2 GND-GND" (solid, remove dead copper, pour order 76): 3900,-3.61 3900,2716.53 556.54,2716.54 ccw(c556.53,2660.06) 536.65,2712.92 56.54,2712.92 ccw(c56.53,2656.39) 0,2656.39 0,46.39 ccw(c50,46.39) 50,-3.61
EXTGND on L6 GND "NONET_L-01_P-001" (solid, remove dead copper, pour order 57): 688.31,766.34 0,766.34 0,50 ccw(c50,50) 50,0 688.31,0
GND on L4 GND "L2 GND-GND" (solid, remove dead copper, pour order 74): 3900,-3.61 3900,2716.53 556.54,2716.54 ccw(c556.53,2660.06) 536.65,2712.92 56.54,2712.92 ccw(c56.53,2656.39) 0,2656.39 0,46.39 ccw(c50,46.39) 50,-3.61
EXTGND on L4 GND "NONET_L-01_P-001" (solid, remove dead copper, pour order 59): 688.31,766.34 0,766.34 0,50 ccw(c50,50) 50,0 688.31,0
GND on L7 GND "L2 GND-GND" (solid, remove dead copper, pour order 77): 3900,-3.61 3900,2716.53 556.54,2716.54 ccw(c556.53,2660.06) 536.65,2712.92 56.54,2712.92 ccw(c56.53,2656.39) 0,2656.39 0,46.39 ccw(c50,46.39) 50,-3.61
EXTGND on L7 GND "NONET_L-01_P-001" (solid, remove dead copper, pour order 60): 688.31,766.34 0,766.34 0,50 ccw(c50,50) 50,0 688.31,0
GND on L9 GND "L2 GND-GND" (solid, remove dead copper, pour order 78): 3900,-3.61 3900,2716.53 556.54,2716.54 ccw(c556.53,2660.06) 536.65,2712.92 56.54,2712.92 ccw(c56.53,2656.39) 0,2656.39 0,46.39 ccw(c50,46.39) 50,-3.61
EXTGND on L9 GND "NONET_L-01_P-001" (solid, remove dead copper, pour order 61): 688.31,766.34 0,766.34 0,50 ccw(c50,50) 50,0 688.31,0
GND on Bottom Layer "L2 GND-GND" (solid, remove dead copper, pour order 82): 3900,-3.61 3900,2716.53 556.54,2716.54 ccw(c556.53,2660.06) 536.65,2712.92 56.54,2712.92 ccw(c56.53,2656.39) 0,2656.39 0,46.39 ccw(c50,46.39) 50,-3.61

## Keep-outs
Keep-Out Layer:
  text ".Layer_Name" at 577,-858.49 h60

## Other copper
Top Layer:
  drawing of 88 lines, arcs and shapes, not listed
  text ".Layer_Name" at 577,-858.49 h60
L2 GND:
  pour cut-out: 2907.99,625.2 ccw(c2882.27,625.27) 2900.45,643.45 ccw(c2882.93,625.93) 2882.93,650.72 2881.55,650.72 ccw(c2881.55,625.98) 2864.06,643.47 2863.35,642.76 ccw(c2880.85,625.27) 2856.11,625.27 2856.11,624.57 ccw(c2881.56,624.57) 2863.56,606.57 2863.7,606.43 ccw(c2882.05,624.77) 2882.05,598.83 ccw(c2882.05,624.75) 2900.38,606.42 2900.75,606.79 ccw(c2883.27,624.27) 2907.99,624.27
  pour cut-out: 2998.18,2238.8 ccw(c2972.46,2238.88) 2990.65,2257.06 ccw(c2973.12,2239.54) 2973.12,2264.32 2971.75,2264.32 ccw(c2971.75,2239.59) 2954.26,2257.08 2953.55,2256.37 ccw(c2971.04,2238.88) 2946.3,2238.88 2946.3,2238.17 ccw(c2971.76,2238.17) 2953.76,2220.17 2953.9,2220.03 ccw(c2972.24,2238.38) 2972.24,2212.44 ccw(c2972.24,2238.36) 2990.58,2220.03 2990.94,2220.4 ccw(c2973.47,2237.87) 2998.18,2237.87
  pour cut-out: 2438.18,2298.8 ccw(c2412.46,2298.88) 2430.65,2317.06 ccw(c2413.12,2299.54) 2413.12,2324.32 2411.75,2324.32 ccw(c2411.75,2299.59) 2394.26,2317.08 2393.55,2316.37 ccw(c2411.04,2298.88) 2386.3,2298.88 2386.3,2298.17 ccw(c2411.76,2298.17) 2393.76,2280.17 2393.9,2280.03 ccw(c2412.24,2298.38) 2412.24,2272.44 ccw(c2412.24,2298.36) 2430.58,2280.03 2430.94,2280.4 ccw(c2413.47,2297.87) 2438.18,2297.87
  pour cut-out: 1888.18,2298.8 ccw(c1862.46,2298.88) 1880.65,2317.06 ccw(c1863.12,2299.54) 1863.12,2324.32 1861.75,2324.32 ccw(c1861.75,2299.59) 1844.26,2317.08 1843.55,2316.37 ccw(c1861.04,2298.88) 1836.3,2298.88 1836.3,2298.17 ccw(c1861.76,2298.17) 1843.76,2280.17 1843.9,2280.03 ccw(c1862.24,2298.38) 1862.24,2272.44 ccw(c1862.24,2298.36) 1880.58,2280.03 1880.94,2280.4 ccw(c1863.47,2297.87) 1888.18,2297.87
  pour cut-out: 2387.73,198.79 ccw(c2413.44,198.72) 2395.26,180.53 ccw(c2412.79,198.06) 2412.79,173.27 2414.16,173.27 ccw(c2414.16,198) 2431.65,180.52 2432.36,181.23 ccw(c2414.86,198.72) 2439.61,198.72 2439.61,199.42 ccw(c2414.15,199.42) 2432.15,217.42 2432.01,217.56 ccw(c2413.67,199.22) 2413.67,225.16 ccw(c2413.67,199.23) 2395.33,217.57 2394.97,217.2 ccw(c2412.44,199.72) 2387.73,199.72
  pour cut-out: 1837.73,198.79 ccw(c1863.44,198.72) 1845.26,180.53 ccw(c1862.79,198.06) 1862.79,173.27 1864.16,173.27 ccw(c1864.16,198) 1881.65,180.52 1882.36,181.23 ccw(c1864.86,198.72) 1889.61,198.72 1889.61,199.42 ccw(c1864.15,199.42) 1882.15,217.42 1882.01,217.56 ccw(c1863.67,199.22) 1863.67,225.16 ccw(c1863.67,199.23) 1845.33,217.57 1844.97,217.2 ccw(c1862.44,199.72) 1837.73,199.72
  pour cut-out: 1261.18,983.77 ccw(c1261.11,958.05) 1242.92,976.24 ccw(c1260.45,958.71) 1235.66,958.71 1235.66,957.33 ccw(c1260.39,957.33) 1242.9,939.85 1243.61,939.14 ccw(c1261.11,956.63) 1261.11,931.89 1261.81,931.89 ccw(c1261.81,957.35) 1279.81,939.35 1279.95,939.49 ccw(c1261.61,957.83) 1287.55,957.83 ccw(c1261.62,957.83) 1279.95,976.16 1279.59,976.53 ccw(c1262.11,959.05) 1262.11,983.77
  pour cut-out: 1261.18,1533.77 ccw(c1261.11,1508.05) 1242.92,1526.24 ccw(c1260.45,1508.71) 1235.66,1508.71 1235.66,1507.33 ccw(c1260.39,1507.33) 1242.9,1489.85 1243.61,1489.14 ccw(c1261.11,1506.63) 1261.11,1481.89 1261.81,1481.89 ccw(c1261.81,1507.35) 1279.81,1489.35 1279.95,1489.49 ccw(c1261.61,1507.83) 1287.55,1507.83 ccw(c1261.62,1507.83) 1279.95,1526.16 1279.59,1526.53 ccw(c1262.11,1509.05) 1262.11,1533.77
  pour cut-out: 2074.96,1833.88 2074.96,1723.88 1999.96,1723.88 1999.96,1833.88
  pour cut-out: 2274.96,1833.88 2274.96,1723.88 2199.96,1723.88 2199.96,1833.88
  pour cut-out: 2274.96,2033.88 2274.96,1923.88 2199.96,1923.88 2199.96,2033.88
  pour cut-out: 2200.95,663.72 2200.95,773.72 2275.95,773.72 2275.95,663.72
  pour cut-out: 2000.95,663.72 2000.95,773.72 2075.95,773.72 2075.95,663.72
  pour cut-out: 2000.95,463.72 2000.95,573.72 2075.95,573.72 2075.95,463.72
  pour cut-out: 1726.11,1295.55 1836.11,1295.55 1836.11,1370.55 1726.11,1370.55
  pour cut-out: 1726.11,1095.55 1836.11,1095.55 1836.11,1170.55 1726.11,1170.55
  pour cut-out: 1526.11,1095.55 1636.11,1095.55 1636.11,1170.55 1526.11,1170.55
  text ".Layer_Name" at 575,-860 h60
